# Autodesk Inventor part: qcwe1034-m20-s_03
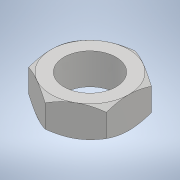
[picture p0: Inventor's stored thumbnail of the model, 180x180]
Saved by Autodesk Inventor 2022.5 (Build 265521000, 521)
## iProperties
Created: 2020-10
Part Number: qcwe1034-m20-s_03
Material: 一般
Document SubType Name: Modeling
Designer: ImaoCorp
Density: 1 g/cm^3
Appearance: 既定
Author: ImaoCorp
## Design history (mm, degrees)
feature "qcwe1034-m20-s_03"
node "ソリッド1"
